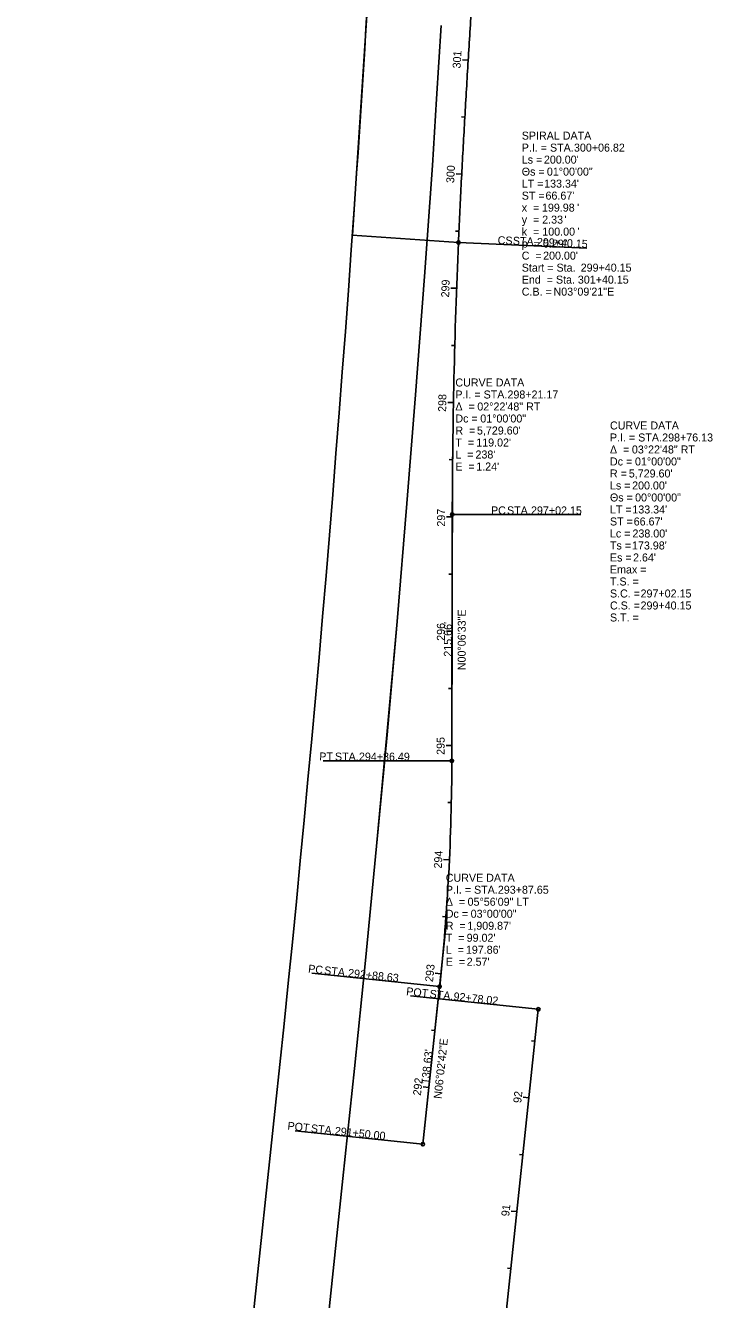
# Model space of a CAD drawing. Extents: x 172104 to 172774, y 250510 to 260293.
# Drawn here: x 172173 to 172774, y 255915 to 257029 of the extents above; entities that cross this region are included whole.
import ezdxf

# ---------------------------------------------------------------- set-up
doc = ezdxf.new("R2010")
doc.units = 0
for name, color, linetype in [('DT_P_Break_Line', 7, 'Continuous'), ('DT_P_Contour_Major', 7, 'Continuous'), ('DT_P_Contour_Minor', 7, 'Continuous'), ('DT_P_Spot_Elevations', 7, 'Continuous'), ('DT_P_Terrain_Boundary', 7, 'Continuous'), ('DT_P_Triangles', 7, 'Continuous'), ('DT_P_Void', 7, 'Continuous'), ('DT_X_Contour_Minor', 7, 'Continuous'), ('DT_X_Spot_Elev', 7, 'Continuous')]:
    doc.layers.add(name, color=color, linetype=linetype)

msp = doc.modelspace()

# ---------------------------------------------------------------- linework, layer by layer
at = {"layer": 'DT_P_Contour_Minor'}
for p, q in [((172546, 256386), (172546.5, 256652.2)), ((172546, 256386), (172546.4, 256601.7)), ((172520.7, 256050.7), (172541.7, 256248.7)), ((172520.7, 256050.7), (172535.3, 256188.5)), ((172553.7, 255526.8), (172621.7, 256168.7))]:
    msp.add_line(p, q, dxfattribs=at)
for centre, radius, start, end in [((178276, 256590.8), 5729.6, 177.51076, 179.89076), ((178276, 256590.8), 5729.6, 177.51076, 179.89076), ((170636.1, 256389.7), 1909.9, 353.955, 359.8908), ((170636.1, 256389.7), 1909.9, 353.955, 359.8908)]:
    msp.add_arc(centre, radius, start, end, dxfattribs=at)
msp.add_open_spline([(172551.8, 256839.6), (172552.5, 256856.3), (172554.1, 256889.6), (172556.8, 256939.5), (172559.7, 256989.4), (172561.8, 257022.7), (172562.8, 257039.3)], degree=3, dxfattribs=at)
msp.add_open_spline([(172551.8, 256839.6), (172552.5, 256856.3), (172554.1, 256889.6), (172556.8, 256939.5), (172559.7, 256989.4), (172561.8, 257022.7), (172562.8, 257039.3)], degree=3, dxfattribs=at)
at = {"layer": 'DT_P_Spot_Elevations'}
for p, q in [((172551.8, 256839.6), (172664.2, 256834.7)), ((172546.4, 256601.7), (172658.9, 256601.5)), ((172546, 256386), (172433.5, 256386.2)), ((172535.3, 256188.5), (172423.5, 256200.4)), ((172621.7, 256168.7), (172509.8, 256180.6)), ((172520.7, 256050.7), (172408.9, 256062.5))]:
    msp.add_line(p, q, dxfattribs=at)
for centre in [(172551.8, 256839.6), (172546.4, 256601.7), (172546, 256386), (172535.3, 256188.5), (172621.7, 256168.7), (172520.7, 256050.7)]:
    msp.add_circle(centre, 1.5, dxfattribs=at)
at = {"layer": 'DT_P_Terrain_Boundary'}
msp.add_line((172172.9, 254022), (172391.8, 256084.9), dxfattribs=at)
msp.add_line((172172.9, 254022), (172391.8, 256084.9), dxfattribs=at)
msp.add_arc((151025.9, 258352.5), 21485.9, 353.94188, 0.0466, dxfattribs=at)
msp.add_arc((151025.9, 258352.5), 21485.9, 353.94188, 0.0466, dxfattribs=at)
at = {"layer": 'DT_P_Triangles'}
for p, q in [((172532.5, 256965.3), (172536.6, 257029.5)), ((172532.6, 256965.3), (172536.7, 257029.5)), ((172529.1, 256907), (172532.5, 256965.3)), ((172529.2, 256907), (172532.6, 256965.3)), ((172522.1, 256809.9), (172529.1, 256907)), ((172522.1, 256809.9), (172529.2, 256907)), ((172514.3, 256706.4), (172522.1, 256809.9)), ((172514.3, 256706.4), (172522.1, 256809.9)), ((172506.7, 256611.3), (172514.3, 256706.4)), ((172506.7, 256611.3), (172514.3, 256706.4)), ((172498.1, 256507.9), (172506.7, 256611.3)), ((172498.2, 256507.9), (172506.7, 256611.3)), ((172489.2, 256408.8), (172498.1, 256507.9)), ((172489.3, 256408.7), (172498.2, 256507.9)), ((172480.2, 256311.3), (172489.2, 256408.8)), ((172480.2, 256311.3), (172489.3, 256408.7)), ((172470.4, 256211.5), (172480.2, 256311.3)), ((172470.5, 256211.5), (172480.2, 256311.3)), ((172460.9, 256117), (172470.4, 256211.5)), ((172460.9, 256117), (172470.5, 256211.5)), ((172450.7, 256020.6), (172460.9, 256117)), ((172450.7, 256020.6), (172460.9, 256117)), ((172439.5, 255914.8), (172450.7, 256020.6)), ((172439.5, 255914.8), (172450.7, 256020.6)), ((172428.8, 255814.8), (172439.5, 255914.8))]:
    msp.add_line(p, q, dxfattribs=at)
at = {"layer": 'DT_P_Void'}
for p, q in [((172560.3, 256999.2), (172555.4, 256999.5)), ((172557.4, 256949.3), (172554.4, 256949.5)), ((172554.7, 256899.4), (172549.7, 256899.6)), ((172552.2, 256849.4), (172549.2, 256849.6)), ((172550.2, 256799.5), (172545.2, 256799.7)), ((172548.6, 256749.5), (172545.6, 256749.6)), ((172547.4, 256699.5), (172542.4, 256699.6)), ((172546.7, 256649.5), (172543.7, 256649.6)), ((172546.4, 256599.5), (172541.4, 256599.5)), ((172546.3, 256549.5), (172543.3, 256549.5)), ((172546.2, 256499.5), (172541.2, 256499.5)), ((172546.1, 256449.5), (172543.1, 256449.5)), ((172546, 256399.5), (172541, 256399.5)), ((172545.5, 256349.5), (172542.5, 256349.6)), ((172543.8, 256299.6), (172538.8, 256299.8)), ((172540.8, 256249.7), (172537.8, 256249.9)), ((172536.5, 256199.8), (172531.5, 256200.3)), ((172531.3, 256150.1), (172528.3, 256150.4)), ((172618.7, 256140.9), (172615.8, 256141.2)), ((172526, 256100.4), (172521, 256100.9)), ((172613.5, 256091.1), (172608.5, 256091.7)), ((172520.7, 256050.7), (172517.8, 256051)), ((172608.2, 256041.4), (172605.2, 256041.7)), ((172602.9, 255991.7), (172598, 255992.2)), ((172597.7, 255942), (172594.7, 255942.3))]:
    msp.add_line(p, q, dxfattribs=at)
at = {"layer": 'DT_X_Contour_Minor'}
msp.add_line((172551.8, 256839.6), (172458.9, 256846.1), dxfattribs=at)
msp.add_arc((151025.9, 258352.5), 21485.9, 355.97974, 359.07307, dxfattribs=at)

# ---------------------------------------------------------------- texts
at = {"layer": 'DT_P_Break_Line'}
for s, rotation, p in [("215.66'", 89.8908, (172546, 256477.2)), ("138.63'", 83.955, (172526.2, 256103))]:
    msp.add_text(s, height=7, rotation=rotation, dxfattribs=at).set_placement(p)
at = {"layer": 'DT_P_Contour_Major'}
for s, rotation, p in [('N00°06\'33"E', 89.8908, (172558.1, 256465.4)), ('N06°02\'42"E', 83.955, (172537, 256090.1))]:
    msp.add_text(s, height=7, rotation=rotation, dxfattribs=at).set_placement(p)
at = {"layer": 'DT_P_Spot_Elevations'}
for s, rotation, p in [('CS', 357.5108, (172586, 256838.2)), (' STA. ', 357.5108, (172596.7, 256837.8)), ('299+40.15', 357.5108, (172620.3, 256836.7)), ('PC', 359.8908, (172580.3, 256601.7)), (' STA. ', 359.8908, (172591.7, 256601.7)), ('297+02.15', 359.8908, (172615.3, 256601.7)), ('PT', 359.8908, (172430, 256386.4)), (' STA. ', 359.8908, (172441.1, 256386.3)), ('294+86.49', 359.8908, (172464.7, 256386.3)), ('PC', 353.955, (172420, 256200.9)), (' STA. ', 353.955, (172431.4, 256199.7)), ('292+88.63', 353.955, (172454.9, 256197.2)), ('POT', 353.955, (172505.8, 256181.1)), (' STA. ', 353.955, (172523.7, 256179.2)), ('92+78.02', 353.955, (172547.2, 256176.7)), ('POT', 353.955, (172401.9, 256063.4)), (' STA. ', 353.955, (172419.8, 256061.5)), ('291+50.00', 353.955, (172443.3, 256059))]:
    msp.add_text(s, height=7, rotation=rotation, dxfattribs=at).set_placement(p)
at = {"layer": 'DT_P_Void'}
for s, rotation, p in [('301', 86.5511, (172553.6, 256991.7)), ('300', 87.0018, (172548, 256891.4)), ('299', 87.9123, (172543.6, 256791.4)), ('298', 88.9123, (172541, 256691.3)), ('297', 89.8908, (172540.1, 256591)), ('296', 89.8908, (172539.9, 256491.1)), ('295', 89.8908, (172539.7, 256391.3)), ('294', 87.296, (172537.2, 256291.7)), ('293', 84.296, (172529.5, 256192.3)), ('292', 83.955, (172518.9, 256092.9)), ('92', 83.955, (172606.7, 256086.4)), ('91', 83.955, (172596.2, 255987.3))]:
    msp.add_text(s, height=7, rotation=rotation, dxfattribs=at).set_placement(p)
at = {"layer": 'DT_X_Spot_Elev'}
for s, p in [('SPIRAL DATA', (172607.2, 256929.6)), ('P.I. = STA. ', (172607.2, 256919.1)), ('300+06.82', (172652.9, 256919.1)), ('Ls = ', (172607.2, 256908.6)), ("200.00'", (172626.6, 256908.6)), ('Θs = ', (172607.2, 256898.1)), ('01°00\'00"', (172629.2, 256898.1)), ('LT = ', (172607.2, 256887.6)), ("133.34'", (172626.8, 256887.6)), ('ST = ', (172607.2, 256877.1)), ("66.67'", (172628, 256877.1)), ('x  = ', (172607.2, 256866.6)), ('199.98', (172624.9, 256866.6)), ("'", (172655.7, 256866.6)), ('y  = ', (172607.2, 256856.1)), ('2.33', (172625.1, 256856.1)), ("'", (172644.6, 256856.1)), ('k  = ', (172607.2, 256845.6)), ('100.00', (172625.2, 256845.6)), ("'", (172655.9, 256845.6)), ('p  = ', (172607.2, 256835.1)), ('0.29', (172625.8, 256835.1)), ("'", (172645.4, 256835.1)), ('C  = ', (172607.2, 256824.6)), ("200.00'", (172625.9, 256824.6)), ('Start = Sta. ', (172607.2, 256814.1)), ('299+40.15', (172658.8, 256814.1)), ('End  = Sta. ', (172607.2, 256803.6)), ('301+40.15', (172656.3, 256803.6)), ('C.B. = ', (172607.2, 256793.1)), ('N03°09\'21"E', (172635, 256793.1)), ('CURVE DATA', (172549.1, 256713.6)), ('P.I. = STA. ', (172549.1, 256703.1)), ('298+21.17', (172594.7, 256703.1)), ('Δ  = ', (172549.1, 256692.6)), ('02°22\'48" RT', (172568.3, 256692.6)), ('Dc = ', (172549.1, 256682.1)), ('01°00\'00"', (172570.9, 256682.1)), ('CURVE DATA', (172684.4, 256676)), ('R  = ', (172549.1, 256671.6)), ("119.02'", (172567.4, 256661.1)), ("5,729.60'", (172568, 256671.6)), ('P.I. = STA. ', (172684.4, 256665.5)), ('298+76.13', (172730.1, 256665.5)), ('T  = ', (172549.1, 256661.1)), ('L  = ', (172549.1, 256650.6)), ("238'", (172566.7, 256650.6)), ('Δ  = ', (172684.4, 256655)), ('03°22\'48" RT', (172703.6, 256655)), ('E  = ', (172549.1, 256640.1)), ("1.24'", (172567.4, 256640.1)), ('Dc = ', (172684.4, 256644.5)), ('01°00\'00"', (172706.3, 256644.5)), ('R = ', (172684.4, 256634)), ("5,729.60'", (172700.9, 256634)), ('Ls = ', (172684.4, 256623.5)), ("200.00'", (172703.8, 256623.5)), ('Θs = ', (172684.4, 256613)), ('00°00\'00"', (172706.4, 256613)), ('LT = ', (172684.4, 256602.5)), ("133.34'", (172704, 256602.5)), ('ST = ', (172684.4, 256592)), ("66.67'", (172705.2, 256592)), ('Lc = ', (172684.4, 256581.5)), ("238.00'", (172704.1, 256581.5)), ('Ts = ', (172684.4, 256571)), ("173.98'", (172703.7, 256571)), ('Es = ', (172684.4, 256560.5)), ('Emax = ', (172684.4, 256550)), ("2.64'", (172704.6, 256560.5)), ('T.S. = ', (172684.4, 256539.5)), ('S.C. = ', (172684.4, 256529)), ('297+02.15', (172711.2, 256529)), ('C.S. = ', (172684.4, 256518.5)), ('299+40.15', (172711.2, 256518.5)), ('S.T. = ', (172684.4, 256508)), ('CURVE DATA', (172540.7, 256280.3)), ('P.I. = STA. ', (172540.7, 256269.8)), ('293+87.65', (172586.3, 256269.8)), ('Δ  = ', (172540.7, 256259.3)), ('Dc = ', (172540.7, 256248.8)), ('05°56\'09" LT', (172559.8, 256259.3)), ('03°00\'00"', (172562.5, 256248.8)), ('R  = ', (172540.7, 256238.3)), ("1,909.87'", (172559.6, 256238.3)), ('T  = ', (172540.7, 256227.8)), ("99.02'", (172559, 256227.8)), ('L  = ', (172540.7, 256217.3)), ("197.86'", (172558.3, 256217.3)), ('E  = ', (172540.7, 256206.8)), ("2.57'", (172559, 256206.8))]:
    msp.add_text(s, height=7, dxfattribs=at).set_placement(p)

doc.saveas('drawing.dxf')
